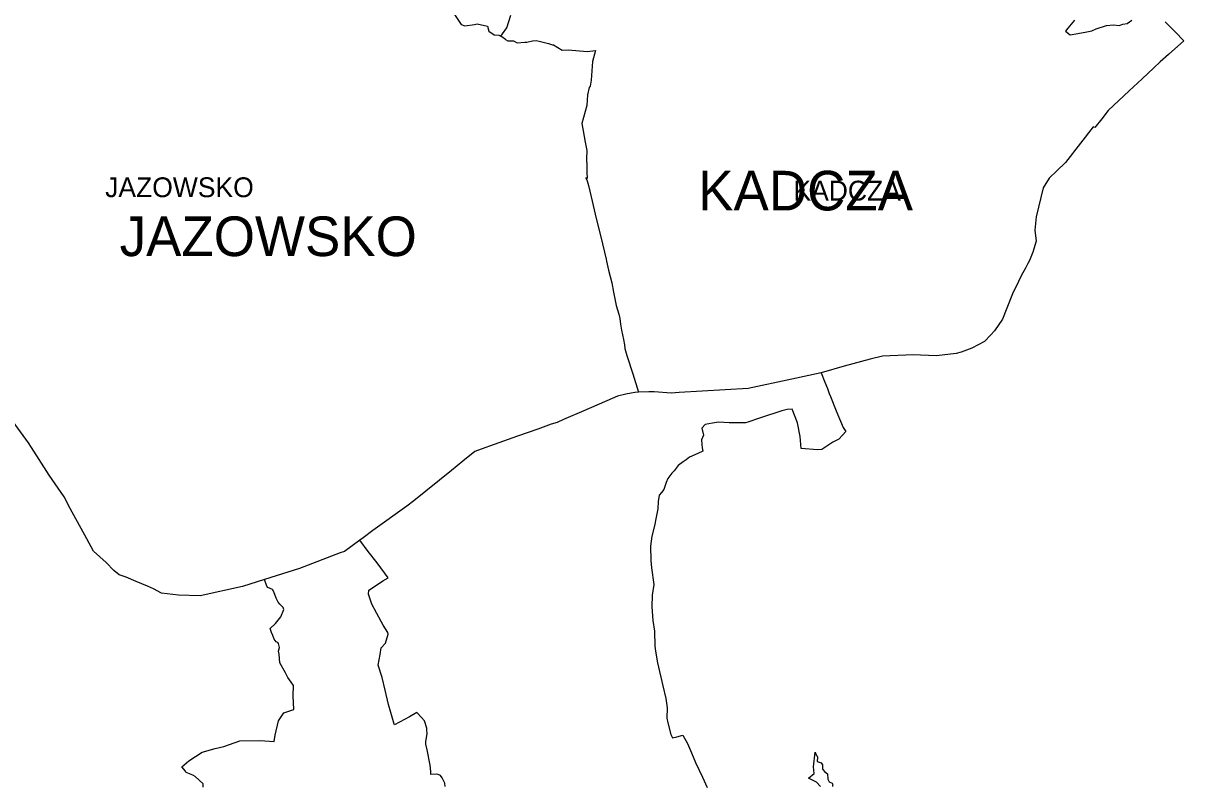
# Model space of a CAD drawing. Extents: x -562952 to -547638, y 190691 to 208158.
# Drawn here: x -552912 to -547638, y 196451 to 199915 of the extents above; entities that cross this region are included whole.
import ezdxf

# ---------------------------------------------------------------- set-up
doc = ezdxf.new("R2010")
doc.units = 0
for name, color, linetype in [('granica_gminy', 7, 'Continuous'), ('granica_sołectwa', 7, 'Continuous'), ('nazwy miejscowości', 7, 'Continuous'), ('nazwy miejscowości DUŻE', 7, 'Continuous'), ('obwódka', 7, 'Continuous')]:
    doc.layers.add(name, color=color, linetype=linetype)

msp = doc.modelspace()

# ---------------------------------------------------------------- linework, layer by layer
at = {"layer": 'granica_gminy'}
for points in [[(-550955.7, 199958.7), (-550921, 199908.9), (-550905.1, 199903.6), (-550860.6, 199909.8), (-550848.4, 199912.8), (-550802.6, 199901.3), (-550795.9, 199878.7), (-550772.1, 199862.5), (-550750.6, 199860.7), (-550742.2, 199856.6), (-550734.4, 199867.6), (-550714.7, 199893.5), (-550696.2, 199952.4)], [(-547721.7, 199921.6), (-547676.1, 199875.5), (-547637.6, 199835.8), (-547707, 199772.7), (-547745, 199739.1), (-547773.6, 199713), (-547826.7, 199662.9), (-547885.3, 199608.5), (-547980.7, 199518.7), (-548010.7, 199480.9), (-548041.9, 199442.1), (-548048.9, 199444.7), (-548107.2, 199370.2), (-548174.8, 199282.7), (-548215.3, 199244), (-548250, 199211.6), (-548276.3, 199167.3), (-548308.5, 199035.9), (-548314.4, 198974.4), (-548309, 198925.5), (-548323.1, 198875.4), (-548339.5, 198837.6), (-548347, 198823.8), (-548356.5, 198803.2), (-548375, 198770.5), (-548389.5, 198741.8), (-548416.3, 198685.4), (-548441.7, 198620.8), (-548460.9, 198571.4), (-548498.3, 198518.4), (-548515, 198500.3), (-548543.7, 198468.6), (-548600.7, 198438.9), (-548649.1, 198421.4), (-548671.6, 198415.2), (-548761.7, 198403.5), (-548834.7, 198407.3), (-548865.9, 198409), (-549007.1, 198402.5), (-549063.5, 198388.7), (-549181.5, 198356.8), (-549285.2, 198327.7), (-549269.1, 198284.6), (-549257.6, 198256.4), (-549248.8, 198233.1), (-549242.8, 198219.1), (-549217.7, 198155), (-549202, 198117.4), (-549197.8, 198107.6), (-549185.3, 198079.3), (-549174, 198060.3), (-549188.3, 198044.2), (-549205.2, 198025.5), (-549232.3, 198011.7), (-549282.6, 197978.2), (-549302.6, 197977.4), (-549375.8, 197982.6), (-549380.5, 198038.4), (-549392.6, 198099.3), (-549417.6, 198162.2), (-549440.1, 198160.8), (-549464.5, 198153.7), (-549496, 198144.2), (-549529.5, 198132.9), (-549574.9, 198117.7), (-549609.9, 198106.1), (-549618.5, 198102.3), (-549628.8, 198099.5), (-549639.1, 198100.1), (-549671.3, 198100.3), (-549684.8, 198099.5), (-549704.1, 198099.9), (-549751.6, 198102.6), (-549779.4, 198098.9), (-549812.1, 198092.3), (-549827.6, 198076.3), (-549820.6, 198044.4), (-549829.1, 198023.3), (-549827.5, 198001.3), (-549826.5, 197986.2), (-549823, 197971.6), (-549846.9, 197960.6), (-549884.6, 197943.4), (-549899, 197932.5), (-549913.2, 197923.4), (-549935.6, 197905.8), (-549954.3, 197881.5), (-549964.8, 197871), (-549982.6, 197846.7), (-549990.5, 197829.6), (-550000.6, 197796.9), (-550011.2, 197783.9), (-550021.9, 197771.4), (-550026.8, 197742.7), (-550028.5, 197709), (-550036.2, 197672), (-550043.8, 197632.7), (-550054.7, 197585.3), (-550060.9, 197539.4), (-550059.5, 197474.5), (-550056.7, 197440.8), (-550046.8, 197365.3), (-550053.6, 197316.4), (-550055.6, 197263.9), (-550050.3, 197202.2), (-550043.7, 197153.7), (-550040.9, 197085.5), (-550039, 197062.7), (-550030.2, 197009.9), (-550004.5, 196905.3), (-549991.1, 196847.4), (-549986, 196805.3), (-549986.3, 196758), (-549982, 196737.1), (-549968.2, 196684.6), (-549961.4, 196668.4), (-549941.7, 196673.4), (-549941.6, 196673.5)], [(-548134.6, 199928.8), (-548164.8, 199893), (-548174.5, 199879.4), (-548153.3, 199862.6), (-548119.1, 199868.2), (-548078.3, 199875.6), (-548056.1, 199880.1), (-548036, 199888.9), (-547988.5, 199905.2), (-547957.5, 199907.3), (-547930.8, 199904.8), (-547914.3, 199910.1), (-547894.5, 199913.4), (-547873.7, 199928.6)], [(-549941.6, 196673.5), (-549914.8, 196681.4), (-549893.4, 196643.3), (-549875.3, 196600.5), (-549856.6, 196556.4), (-549824.8, 196489.7), (-549803.3, 196443.6)], [(-549289.2, 196447.6), (-549307.2, 196467.8), (-549342.6, 196485.8), (-549317.2, 196507.3), (-549321.2, 196537), (-549313.3, 196603.5), (-549307.9, 196591.3), (-549305, 196588), (-549302.1, 196580.7), (-549303.2, 196561.5), (-549286, 196554.9), (-549279.3, 196546.1), (-549280.1, 196536.5), (-549279.6, 196527.2), (-549269.1, 196514.8), (-549256.6, 196505.7), (-549254.6, 196481.9), (-549248.8, 196469.7), (-549235, 196462.9), (-549232.3, 196457.5), (-549233.9, 196454.2), (-549234.4, 196447.7)]]:
    msp.add_lwpolyline(points, dxfattribs=at)
at = {"layer": 'granica_sołectwa'}
for p, q in [((-551343.7, 197516.1), (-551382.5, 197566.9)), ((-551304.2, 197464.4), (-551343.7, 197516.1)), ((-551253.5, 197396.4), (-551304.2, 197464.4)), ((-551298.1, 197368.5), (-551277.3, 197382)), ((-551277.3, 197382), (-551253.5, 197396.4)), ((-551343.3, 197321.4), (-551340.9, 197340.5)), ((-551341.7, 197317.1), (-551343.3, 197321.4)), ((-551340.9, 197340.5), (-551298.1, 197368.5)), ((-551327.6, 197276.1), (-551341.7, 197317.1)), ((-551305.4, 197233.4), (-551327.6, 197276.1)), ((-551275.6, 197181), (-551305.4, 197233.4)), ((-551255, 197148.2), (-551275.6, 197181)), ((-551265.2, 197099.7), (-551252.8, 197140.5)), ((-551252.8, 197140.5), (-551255, 197148.2)), ((-551289.4, 197047.8), (-551284.7, 197077.3)), ((-551284.7, 197077.3), (-551265.2, 197099.7)), ((-551298.4, 196998.7), (-551289.4, 197047.8)), ((-551280.1, 196942.7), (-551298.4, 196998.7)), ((-551267.1, 196885.1), (-551280.1, 196942.7)), ((-551251.7, 196821.1), (-551267.1, 196885.1)), ((-551241, 196784.5), (-551251.7, 196821.1)), ((-551225.6, 196731.2), (-551241, 196784.5)), ((-551157.2, 196764.9), (-551225.2, 196727.5)), ((-551122.6, 196783.8), (-551157.2, 196764.9)), ((-551225.2, 196727.5), (-551225.6, 196731.2))]:
    msp.add_line(p, q, dxfattribs=at)
for points in [[(-550719.5, 199841), (-550736.7, 199852.8), (-550742.2, 199856.6)], [(-550719.5, 199841), (-550709.5, 199835), (-550683.8, 199834.9)], [(-550683.8, 199834.9), (-550667.6, 199825.8), (-550633, 199829.1), (-550622.8, 199829.6), (-550596.9, 199835.4), (-550581.3, 199836.6), (-550567.8, 199833.7), (-550525.2, 199823.1), (-550506.3, 199817.7), (-550502.4, 199816.5), (-550462, 199792.6), (-550435, 199795), (-550349, 199786.4), (-550310.9, 199791)], [(-550310.9, 199791), (-550325.3, 199740.7), (-550331.3, 199656.5), (-550335.5, 199628.9), (-550339.5, 199622.5), (-550347.2, 199589.3), (-550351.2, 199541.7), (-550372.7, 199459.7), (-550366.6, 199427), (-550357.6, 199375.3), (-550350.8, 199337.1), (-550351.5, 199299.4), (-550351.2, 199267.7), (-550349.9, 199230.6), (-550348.5, 199217.2), (-550348.5, 199209.5), (-550354.5, 199212.7), (-550349.5, 199198.8), (-550343.1, 199177.6), (-550331.6, 199126.5), (-550308.3, 199028.1), (-550286.9, 198944.4), (-550263.5, 198843), (-550261.4, 198834.4), (-550251.8, 198793.9), (-550236.7, 198735.3), (-550229.9, 198693.9), (-550216.6, 198633.3), (-550205.5, 198592.8), (-550201.2, 198574.1), (-550196.9, 198547.7), (-550192.7, 198520.5), (-550183.5, 198478.1), (-550179.8, 198453.8), (-550178.5, 198437.3), (-550168.8, 198406.1), (-550142.2, 198322.9), (-550115.5, 198239.7)], [(-552283.3, 197326.8), (-552319.9, 197346.3), (-552347.6, 197357.8), (-552398.6, 197378.8), (-552444.7, 197398.1), (-552476, 197409.7), (-552500.2, 197428.9), (-552534.5, 197465.1), (-552592.6, 197516.5), (-552622.6, 197573.5), (-552698.5, 197710.1), (-552726.3, 197763.8), (-552794.1, 197862.8), (-552874.4, 197988.5), (-552888.5, 198008.4), (-552960.4, 198108.6), (-553029.7, 198200.8), (-553085, 198272.8), (-553100, 198294.1), (-553156.5, 198351), (-553182.8, 198378.3)], [(-549285.2, 198327.7), (-549419.7, 198298.2), (-549618.1, 198255.1), (-549930.4, 198237.7), (-549967.8, 198235.4), (-550044.3, 198241.3), (-550068.4, 198241), (-550115.8, 198239.6), (-550132.5, 198238.4), (-550149.4, 198235.3), (-550173.7, 198229.8), (-550210.9, 198221.2), (-550235.3, 198210.3), (-550364.3, 198154.6), (-550455.9, 198114.9), (-550486, 198101.8), (-550513.2, 198093.1), (-550573.2, 198071.8), (-550666.3, 198039.1), (-550771.6, 198001.2), (-550831.2, 197979.8), (-550859.6, 197969.6), (-550913.9, 197926.2), (-550966.1, 197884.1), (-551137.3, 197746.1), (-551168.9, 197721.9), (-551323, 197610.2), (-551367.6, 197577.7), (-551382.5, 197566.9), (-551451.9, 197516.1), (-551471.6, 197508.7), (-551655.9, 197438.8), (-551814.9, 197387.7), (-551915.3, 197356.7), (-552107.4, 197314.3), (-552207.1, 197316.4), (-552283.3, 197326.8)], [(-552098.4, 196603.9), (-552039.2, 196620.3), (-551999.6, 196630), (-551927.6, 196655), (-551834.9, 196656.6), (-551772.2, 196652.5), (-551766.5, 196681.1), (-551751.7, 196745.5), (-551727.7, 196783.2), (-551682.2, 196798.4), (-551684.8, 196859.5), (-551683.4, 196906), (-551694, 196921.3), (-551709, 196943.2), (-551719.4, 196964.5), (-551746.2, 197010.3), (-551749.2, 197049.3), (-551751.8, 197062.7), (-551746.8, 197079.5), (-551752.6, 197097.4), (-551755.4, 197102.5), (-551762.3, 197104.5), (-551771.1, 197116.7), (-551777.9, 197134.4), (-551783.9, 197147.1), (-551790.5, 197165.8), (-551765.5, 197188.5), (-551741.1, 197218.1), (-551727.2, 197252.5), (-551730.4, 197261.7), (-551746.2, 197275.7), (-551753.3, 197285.4), (-551762.7, 197303.3), (-551773.3, 197331.5), (-551779.2, 197343), (-551800.4, 197351.5), (-551805.6, 197358.2), (-551814.9, 197387.7)], [(-550993.7, 196448.1), (-550995.7, 196463.2), (-551007.5, 196487.7), (-551015.2, 196498.4), (-551025.7, 196503), (-551035.2, 196504.4), (-551059.7, 196502.7), (-551059.9, 196516), (-551062.5, 196545.4), (-551076.1, 196614.9), (-551081.8, 196640.2), (-551082.3, 196651.1), (-551077.5, 196679.1), (-551076.9, 196686.6), (-551077.5, 196705.1), (-551077.5, 196712.5), (-551088.4, 196746.2), (-551102.2, 196761.5), (-551122.5, 196783.7), (-551122.6, 196783.8)], [(-552094.3, 196444.8), (-552094.9, 196459.6), (-552129.9, 196493.8), (-552140.6, 196500.1), (-552172.2, 196511.8), (-552174.9, 196517.3), (-552190.6, 196537.6), (-552159.7, 196564.2), (-552098.4, 196603.9)]]:
    msp.add_lwpolyline(points, dxfattribs=at)
at = {"layer": 'obwódka'}
for points in [[(-550955.7, 199958.7), (-550921, 199908.9), (-550905.1, 199903.6), (-550860.6, 199909.8), (-550848.4, 199912.8), (-550802.6, 199901.3), (-550795.9, 199878.7), (-550772.1, 199862.5), (-550750.6, 199860.7), (-550742.2, 199856.6), (-550734.4, 199867.6), (-550714.7, 199893.5), (-550696.2, 199952.4)], [(-547721.7, 199921.6), (-547676.1, 199875.5), (-547637.6, 199835.8), (-547707, 199772.7), (-547745, 199739.1), (-547773.6, 199713), (-547826.7, 199662.9), (-547885.3, 199608.5), (-547980.7, 199518.7), (-548010.7, 199480.9), (-548041.9, 199442.1), (-548048.9, 199444.7), (-548107.2, 199370.2), (-548174.8, 199282.7), (-548215.3, 199244), (-548250, 199211.6), (-548276.3, 199167.3), (-548308.5, 199035.9), (-548314.4, 198974.4), (-548309, 198925.5), (-548323.1, 198875.4), (-548339.5, 198837.6), (-548347, 198823.8), (-548356.5, 198803.2), (-548375, 198770.5), (-548389.5, 198741.8), (-548416.3, 198685.4), (-548441.7, 198620.8), (-548460.9, 198571.4), (-548498.3, 198518.4), (-548515, 198500.3), (-548543.7, 198468.6), (-548600.7, 198438.9), (-548649.1, 198421.4), (-548671.6, 198415.2), (-548761.7, 198403.5), (-548834.7, 198407.3), (-548865.9, 198409), (-549007.1, 198402.5), (-549063.5, 198388.7), (-549181.5, 198356.8), (-549285.2, 198327.7), (-549269.1, 198284.6), (-549257.6, 198256.4), (-549248.8, 198233.1), (-549242.8, 198219.1), (-549217.7, 198155), (-549202, 198117.4), (-549197.8, 198107.6), (-549185.3, 198079.3), (-549174, 198060.3), (-549188.3, 198044.2), (-549205.2, 198025.5), (-549232.3, 198011.7), (-549282.6, 197978.2), (-549302.6, 197977.4), (-549375.8, 197982.6), (-549380.5, 198038.4), (-549392.6, 198099.3), (-549417.6, 198162.2), (-549440.1, 198160.8), (-549464.5, 198153.7), (-549496, 198144.2), (-549529.5, 198132.9), (-549574.9, 198117.7), (-549609.9, 198106.1), (-549618.5, 198102.3), (-549628.8, 198099.5), (-549639.1, 198100.1), (-549671.3, 198100.3), (-549684.8, 198099.5), (-549704.1, 198099.9), (-549751.6, 198102.6), (-549779.4, 198098.9), (-549812.1, 198092.3), (-549827.6, 198076.3), (-549820.6, 198044.4), (-549829.1, 198023.3), (-549827.5, 198001.3), (-549826.5, 197986.2), (-549823, 197971.6), (-549846.9, 197960.6), (-549884.6, 197943.4), (-549899, 197932.5), (-549913.2, 197923.4), (-549935.6, 197905.8), (-549954.3, 197881.5), (-549964.8, 197871), (-549982.6, 197846.7), (-549990.5, 197829.6), (-550000.6, 197796.9), (-550011.2, 197783.9), (-550021.9, 197771.4), (-550026.8, 197742.7), (-550028.5, 197709), (-550036.2, 197672), (-550043.8, 197632.7), (-550054.7, 197585.3), (-550060.9, 197539.4), (-550059.5, 197474.5), (-550056.7, 197440.8), (-550046.8, 197365.3), (-550053.6, 197316.4), (-550055.6, 197263.9), (-550050.3, 197202.2), (-550043.7, 197153.7), (-550040.9, 197085.5), (-550039, 197062.7), (-550030.2, 197009.9), (-550004.5, 196905.3), (-549991.1, 196847.4), (-549986, 196805.3), (-549986.3, 196758), (-549982, 196737.1), (-549968.2, 196684.6), (-549961.4, 196668.4), (-549941.7, 196673.4), (-549941.6, 196673.5)], [(-548134.6, 199928.8), (-548164.8, 199893), (-548174.5, 199879.4), (-548153.3, 199862.6), (-548119.1, 199868.2), (-548078.3, 199875.6), (-548056.1, 199880.1), (-548036, 199888.9), (-547988.5, 199905.2), (-547957.5, 199907.3), (-547930.8, 199904.8), (-547914.3, 199910.1), (-547894.5, 199913.4), (-547873.7, 199928.6)], [(-549941.6, 196673.5), (-549914.8, 196681.4), (-549893.4, 196643.3), (-549875.3, 196600.5), (-549856.6, 196556.4), (-549824.8, 196489.7), (-549803.3, 196443.6)], [(-549289.2, 196447.6), (-549307.2, 196467.8), (-549342.6, 196485.8), (-549317.2, 196507.3), (-549321.2, 196537), (-549313.3, 196603.5), (-549307.9, 196591.3), (-549305, 196588), (-549302.1, 196580.7), (-549303.2, 196561.5), (-549286, 196554.9), (-549279.3, 196546.1), (-549280.1, 196536.5), (-549279.6, 196527.2), (-549269.1, 196514.8), (-549256.6, 196505.7), (-549254.6, 196481.9), (-549248.8, 196469.7), (-549235, 196462.9), (-549232.3, 196457.5), (-549233.9, 196454.2), (-549234.4, 196447.7)]]:
    msp.add_lwpolyline(points, dxfattribs=at)

# ---------------------------------------------------------------- texts
at = {"layer": 'nazwy miejscowości'}
for s, p in [('JAZOWSKO', (-552539.7, 199125)), ('KADCZA', (-549411.6, 199109.7))]:
    msp.add_text(s, height=90, dxfattribs=at).set_placement(p)
at = {"layer": 'nazwy miejscowości DUŻE'}
for s, p in [('KADCZA', (-549844.6, 199064.7)), ('JAZOWSKO', (-552473.9, 198857.3))]:
    msp.add_text(s, height=180, dxfattribs=at).set_placement(p)

doc.saveas('drawing.dxf')
